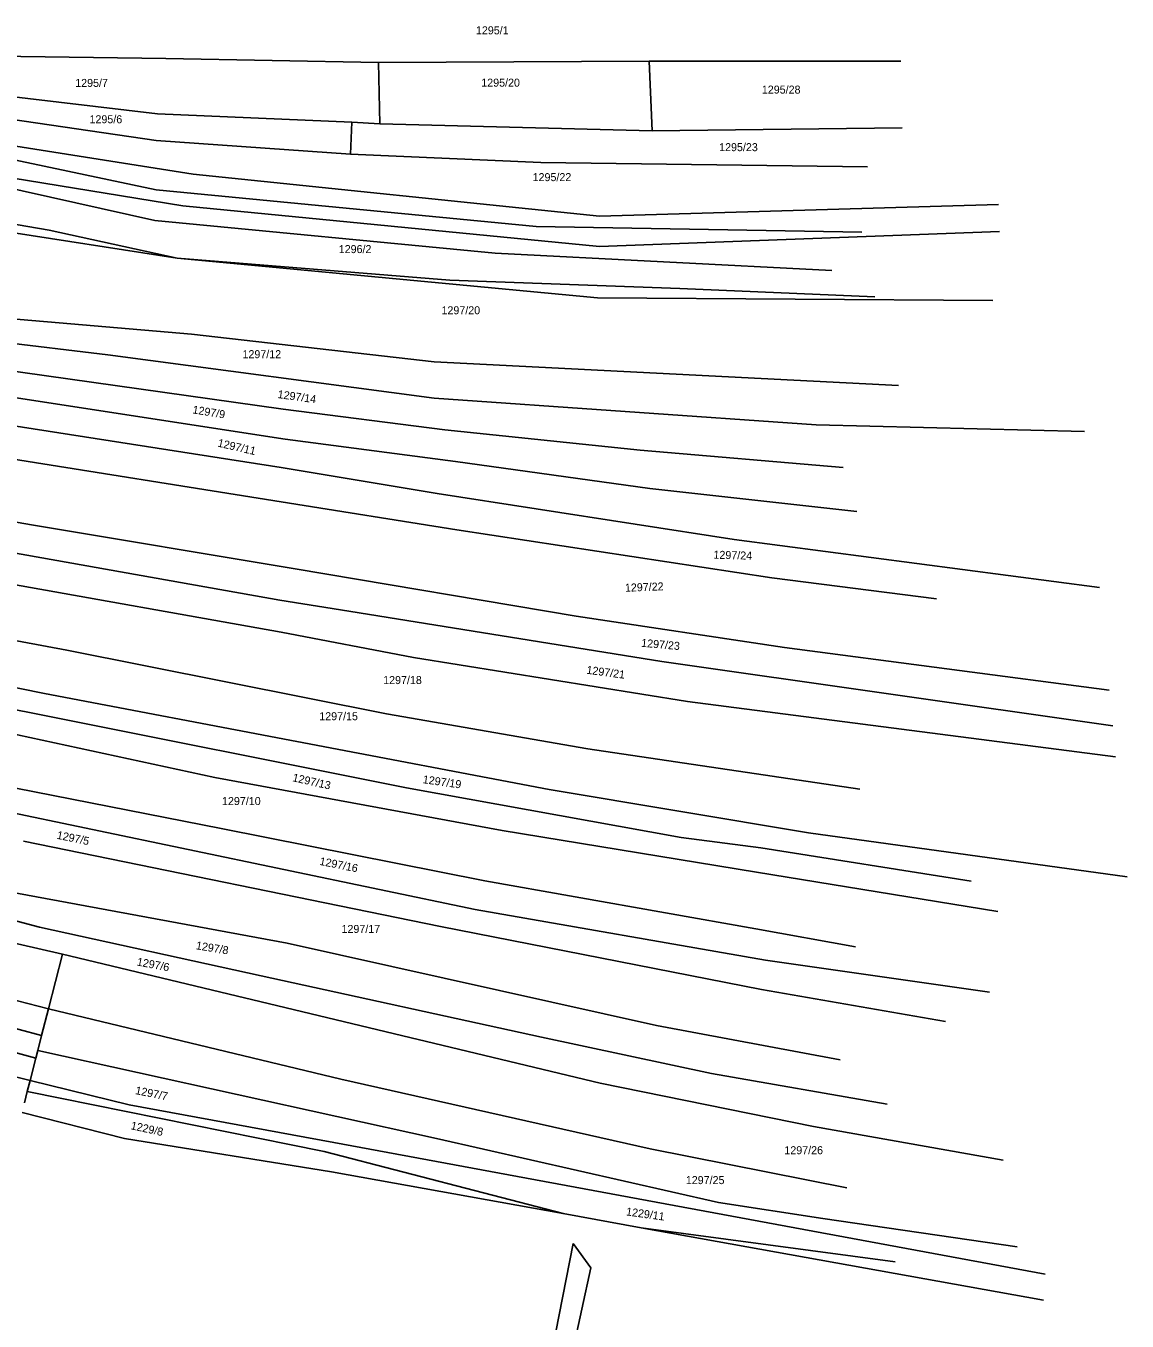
# Model space of a CAD drawing. Extents: x -563148 to -561712, y -1182311 to -1179502.
# Drawn here: x -562032.9 to -561826.4, y -1181017.2 to -1180774.4 of the extents above; entities that cross this region are included whole.
import ezdxf

# ---------------------------------------------------------------- set-up
doc = ezdxf.new("R2010")
doc.units = 0
doc.layers.add('Vrstva 55', color=7, linetype='Continuous')
doc.layers.add('Vrstva 57', color=7, linetype='Continuous')

msp = doc.modelspace()

# ---------------------------------------------------------------- linework, layer by layer
at = {"layer": 'Vrstva 55'}
for p, q in [((-562118.86, -1180779.04), (-562006.69, -1180780.45)), ((-561966.83, -1180781.24), (-562006.69, -1180780.45)), ((-561916.03, -1180780.97), (-561966.83, -1180781.24)), ((-561966.57, -1180792.7), (-561966.83, -1180781.24)), ((-561915.5, -1180794.01), (-561916.03, -1180780.97)), ((-561868.87, -1180780.97), (-561916.03, -1180780.97)), ((-562052.93, -1180785.54), (-562008.25, -1180790.88)), ((-562008.51, -1180795.83), (-562054.88, -1180789.05)), ((-562075.28, -1180790.5), (-562001.59, -1180802.15)), ((-561971.78, -1180792.44), (-562008.25, -1180790.88)), ((-561972.04, -1180798.44), (-561971.78, -1180792.44)), ((-561966.57, -1180792.7), (-561971.78, -1180792.44)), ((-561915.5, -1180794.01), (-561966.57, -1180792.7)), ((-561868.61, -1180793.48), (-561915.5, -1180794.01)), ((-562003.52, -1180808.08), (-562078.19, -1180796.02)), ((-562008.51, -1180805.1), (-562047.85, -1180796.76)), ((-561972.04, -1180798.44), (-562008.51, -1180795.83)), ((-561936.35, -1180800), (-561972.04, -1180798.44)), ((-562053.32, -1180800.93), (-562008.77, -1180810.83)), ((-561875.12, -1180800.78), (-561936.35, -1180800)), ((-562001.59, -1180802.15), (-561925.35, -1180810.02)), ((-562004.54, -1180817.94), (-562077.26, -1180806.57)), ((-562028.57, -1180812.66), (-562066.35, -1180806.14)), ((-561937.26, -1180812), (-562008.51, -1180805.1)), ((-561925.37, -1180815.71), (-562003.52, -1180808.08)), ((-561925.35, -1180810.02), (-561850.55, -1180807.88)), ((-562008.77, -1180810.83), (-561944.94, -1180816.96)), ((-562004.54, -1180817.94), (-562028.57, -1180812.66)), ((-561876.16, -1180813.05), (-561937.26, -1180812)), ((-561850.36, -1180812.92), (-561925.37, -1180815.71)), ((-561953.41, -1180822.04), (-562004.54, -1180817.94)), ((-561925.72, -1180825.34), (-562004.54, -1180817.94)), ((-561944.94, -1180816.96), (-561881.76, -1180820.21)), ((-561910.29, -1180823.6), (-561953.41, -1180822.04)), ((-561873.69, -1180825.17), (-561910.29, -1180823.6)), ((-561851.62, -1180825.84), (-561925.72, -1180825.34)), ((-562001.86, -1180832.13), (-562054.68, -1180827.69)), ((-562017.55, -1180836.06), (-562067.76, -1180830.04)), ((-561956.37, -1180837.36), (-562001.86, -1180832.13)), ((-561984.67, -1180846.19), (-562063.24, -1180835.2)), ((-561956.37, -1180844.17), (-562017.55, -1180836.06)), ((-561869.29, -1180841.81), (-561956.37, -1180837.36)), ((-561985.06, -1180863.59), (-562112.92, -1180843.18)), ((-562056.11, -1180840.85), (-561984.28, -1180851.82)), ((-561985.06, -1180857.18), (-562063.64, -1180844.88)), ((-561884.72, -1180849.14), (-561956.37, -1180844.17)), ((-561954.34, -1180850.12), (-561984.67, -1180846.19)), ((-561917.73, -1180853.91), (-561954.34, -1180850.12)), ((-561884.72, -1180849.14), (-561834.38, -1180850.38)), ((-561952.38, -1180856), (-561984.28, -1180851.82)), ((-562031.87, -1180867.9), (-562115.67, -1180853.64)), ((-561879.69, -1180857.18), (-561917.73, -1180853.91)), ((-561955.78, -1180862.02), (-561985.06, -1180857.18)), ((-561915.9, -1180861.1), (-561952.38, -1180856)), ((-561900.08, -1180870.65), (-561955.78, -1180862.02)), ((-561877.07, -1180865.42), (-561915.9, -1180861.1)), ((-561985.06, -1180888.05), (-562121.29, -1180863.72)), ((-561952.12, -1180868.82), (-561985.06, -1180863.59)), ((-561982.45, -1180876.14), (-562031.87, -1180867.9)), ((-561893.02, -1180877.84), (-561952.12, -1180868.82)), ((-561985.32, -1180882.03), (-562044.02, -1180871.56)), ((-561900.08, -1180870.65), (-561831.59, -1180879.64)), ((-562025.27, -1180891.38), (-562122.73, -1180873.39)), ((-561929.76, -1180885.04), (-561982.45, -1180876.14)), ((-562153.43, -1180879.23), (-562032.26, -1180903.08)), ((-561862.17, -1180881.77), (-561893.02, -1180877.84)), ((-562029.45, -1180899.49), (-562121.16, -1180881.24)), ((-561973.95, -1180883.86), (-561985.32, -1180882.03)), ((-561913.68, -1180893.54), (-561973.95, -1180883.86)), ((-561890.67, -1180890.92), (-561929.76, -1180885.04)), ((-561960.22, -1180892.76), (-561985.06, -1180888.05)), ((-561965.32, -1180903.35), (-562025.27, -1180891.38)), ((-561890.67, -1180890.92), (-561829.75, -1180898.92)), ((-561908.84, -1180901), (-561960.22, -1180892.76)), ((-561913.68, -1180893.54), (-561829.11, -1180905.57)), ((-561934.79, -1180917.54), (-562029.45, -1180899.49)), ((-561908.84, -1180901), (-561828.56, -1180911.39)), ((-561961.53, -1180917.21), (-562032.26, -1180903.08)), ((-561927.54, -1180909.89), (-561965.32, -1180903.35)), ((-561997.48, -1180915.25), (-562036.83, -1180906.75)), ((-561876.55, -1180917.48), (-561927.54, -1180909.89)), ((-561943.62, -1180925.19), (-561997.48, -1180915.25)), ((-561996.3, -1180924.8), (-562038.4, -1180916.56)), ((-561910.02, -1180926.5), (-561961.53, -1180917.21)), ((-561886.16, -1180925.65), (-561934.79, -1180917.54)), ((-561948.65, -1180940.03), (-562038.6, -1180921.2)), ((-561946.88, -1180934.61), (-561996.3, -1180924.8)), ((-561895.9, -1180933.03), (-561943.62, -1180925.19)), ((-561826.41, -1180933.88), (-561886.16, -1180925.65)), ((-561955.19, -1180943.17), (-562033.37, -1180927.22)), ((-561895.12, -1180928.45), (-561910.02, -1180926.5)), ((-561855.63, -1180934.73), (-561895.12, -1180928.45)), ((-561850.67, -1180940.36), (-561895.9, -1180933.03)), ((-562030.37, -1180943.3), (-562066.1, -1180934.09)), ((-561983.95, -1180946.31), (-562044.88, -1180935.06)), ((-561896.03, -1180943.63), (-561946.88, -1180934.61)), ((-562029.98, -1180963.66), (-562126.67, -1180937.74)), ((-562026.05, -1180948.4), (-562064.67, -1180939.56)), ((-561894.2, -1180949.51), (-561948.65, -1180940.03)), ((-562028.69, -1180958.65), (-562090.85, -1180942.43)), ((-561988.79, -1180952.45), (-562030.37, -1180943.3)), ((-561894.99, -1180955), (-561955.19, -1180943.17)), ((-561877.34, -1180947.03), (-561896.03, -1180943.63)), ((-562031.07, -1180967.89), (-562114.76, -1180945.3)), ((-561914.66, -1180961.75), (-561983.95, -1180946.31)), ((-562026.05, -1180948.4), (-562028.69, -1180958.65)), ((-562026.05, -1180948.4), (-561925.25, -1180972.59)), ((-561852.23, -1180955.53), (-561894.2, -1180949.51)), ((-561936.23, -1180963.96), (-561988.79, -1180952.45)), ((-562109.22, -1180953.2), (-562032.14, -1180972.07)), ((-561860.47, -1180961.02), (-561894.99, -1180955)), ((-562028.69, -1180958.65), (-562029.98, -1180963.66)), ((-562028.69, -1180958.65), (-561973.89, -1180971.81)), ((-561880.21, -1180968.21), (-561914.66, -1180961.75)), ((-562029.98, -1180963.66), (-562030.7, -1180966.46)), ((-561904.33, -1180970.76), (-561936.23, -1180963.96)), ((-562030.7, -1180966.46), (-562031.07, -1180967.89)), ((-561955.9, -1180982.97), (-562030.7, -1180966.46)), ((-562031.07, -1180967.89), (-562032.14, -1180972.07)), ((-561973.89, -1180971.81), (-561915.84, -1180984.89)), ((-561871.39, -1180976.52), (-561904.33, -1180970.76)), ((-562033.18, -1180976.23), (-562032.68, -1180974.16)), ((-562032.14, -1180972.07), (-562032.68, -1180974.16)), ((-562032.68, -1180974.16), (-561977.02, -1180985.41)), ((-562032.14, -1180972.07), (-562013.58, -1180976.62)), ((-561925.25, -1180972.59), (-561885.25, -1180980.7)), ((-562013.58, -1180976.62), (-561975.18, -1180983.69)), ((-562033.62, -1180978.06), (-562014.41, -1180982.94)), ((-561885.25, -1180980.7), (-561849.68, -1180986.98)), ((-561975.61, -1180989.2), (-562014.41, -1180982.94)), ((-561975.18, -1180983.69), (-561841.78, -1181008.35)), ((-561903.01, -1180994.96), (-561955.9, -1180982.97)), ((-561977.02, -1180985.41), (-561932.17, -1180997.03)), ((-561915.84, -1180984.89), (-561878.97, -1180992.21)), ((-561975.61, -1180989.2), (-561932.17, -1180997.03)), ((-561883.48, -1180997.91), (-561903.01, -1180994.96)), ((-561932.17, -1180997.03), (-561917.53, -1180999.67)), ((-561847.01, -1181003.27), (-561883.48, -1180997.91)), ((-561917.53, -1180999.67), (-561842.08, -1181013.28)), ((-561917.53, -1180999.67), (-561869.93, -1181006.04)), ((-561936.8, -1181035.7), (-561930.3, -1181002.6)), ((-561930.3, -1181002.6), (-561927, -1181007.2)), ((-561927, -1181007.2), (-561933.4, -1181036.9))]:
    msp.add_line(p, q, dxfattribs=at)

# ---------------------------------------------------------------- texts
at = {"layer": 'Vrstva 57'}
for s, p in [('1295/1', (-561948.53, -1180775.95)), ('1295/7', (-562023.68, -1180785.81)), ('1295/20', (-561947.53, -1180785.76)), ('1295/28', (-561894.91, -1180787.06)), ('1295/6', (-562021, -1180792.62)), ('1295/23', (-561902.92, -1180797.85)), ('1295/22', (-561937.9, -1180803.47)), ('1296/2', (-561974.26, -1180816.96)), ('1297/20', (-561954.99, -1180828.43)), ('1297/12', (-561992.31, -1180836.66)), ('1297/18', (-561965.93, -1180897.75)), ('1297/15', (-561977.91, -1180904.53)), ('1297/10', (-561996.15, -1180920.43)), ('1297/17', (-561973.74, -1180944.41)), ('1297/26', (-561890.69, -1180985.89)), ('1297/25', (-561909.17, -1180991.49))]:
    msp.add_text(s, height=1.5, dxfattribs=at).set_placement(p)
for s, rotation, p in [('1297/14', 352.0304, (-561985.79, -1180844.12)), ('1297/9', 350.6792, (-562001.76, -1180846.99)), ('1297/11', 346.9927, (-561997.07, -1180853.21)), ('1297/24', 358.3732, (-561904, -1180874.24)), ('1297/22', 2.2605, (-561920.56, -1180880.46)), ('1297/23', 354.9869, (-561917.58, -1180890.75)), ('1297/21', 352.417, (-561927.87, -1180895.8)), ('1297/13', 347.3806, (-561983.03, -1180915.95)), ('1297/19', 351.9679, (-561958.57, -1180916.32)), ('1297/5', 348.3161, (-562027.23, -1180926.73)), ('1297/16', 348.6621, (-561977.95, -1180931.63)), ('1297/8', 350.5974, (-562001.12, -1180947.45)), ('1297/6', 349.3346, (-562012.21, -1180950.49)), ('1297/7', 348.5905, (-562012.5, -1180974.6)), ('1229/8', 347.766, (-562013.36, -1180981.19)), ('1229/11', 352.0949, (-561920.44, -1180997.34))]:
    msp.add_text(s, height=1.5, rotation=rotation, dxfattribs=at).set_placement(p)

doc.saveas('drawing.dxf')
